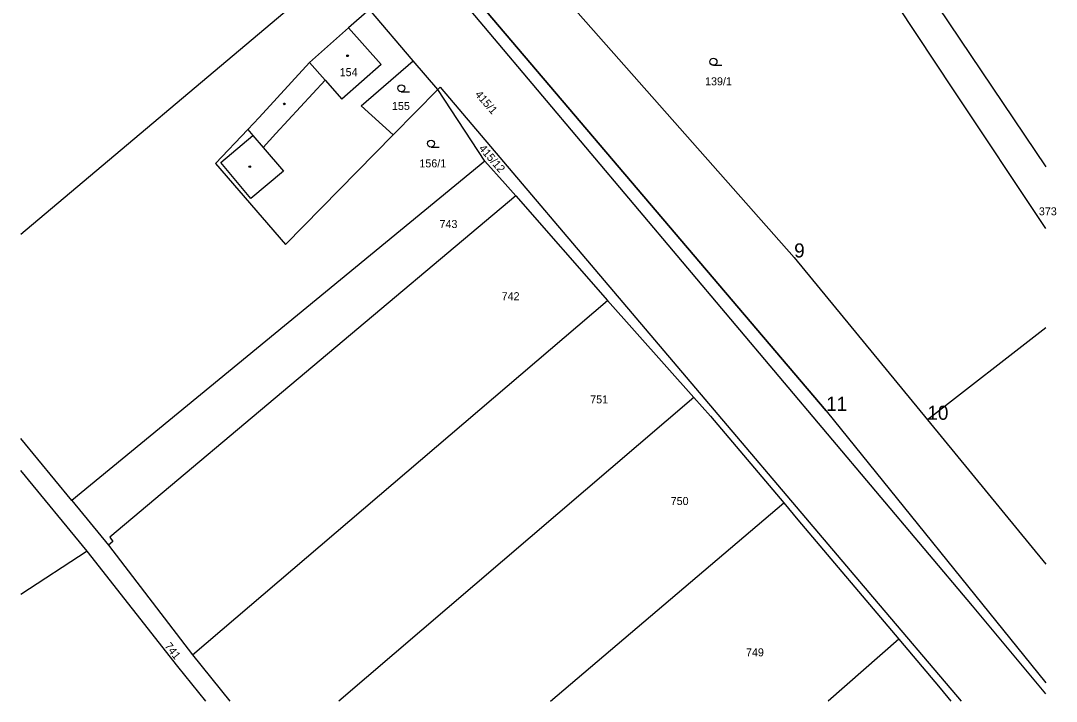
# Model space of a CAD drawing. Extents: x -504601 to -503665, y -1079870 to -1078626.
# Drawn here: x -504599.7 to -504379.8, y -1078928.2 to -1078783.7 of the extents above; entities that cross this region are included whole.
import ezdxf

# ---------------------------------------------------------------- set-up
doc = ezdxf.new("R2010")
doc.units = 0
for name, color, linetype in [('Hranice parcel', 7, 'Continuous'), ('Parcelní čísla', 7, 'Continuous'), ('Vnitřní kresba', 7, 'Continuous'), ('Vrstva 31', 7, 'Continuous'), ('Vrstva 32', 7, 'Continuous'), ('Vrstva 54', 7, 'Continuous'), ('Značky budov', 7, 'Continuous'), ('Značky kultur', 7, 'Continuous')]:
    doc.layers.add(name, color=color, linetype=linetype)

msp = doc.modelspace()

# ---------------------------------------------------------------- linework, layer by layer
at = {"layer": 'Hranice parcel'}
for p, q in [((-504599.72, -1078829.02), (-504538.29, -1078777.24)), ((-504516.36, -1078792.2), (-504525.66, -1078781.28)), ((-504511.18, -1078798.28), (-504516.36, -1078792.2)), ((-504520.67, -1078807.94), (-504511.18, -1078798.28)), ((-504511.18, -1078798.28), (-504510.65, -1078797.8)), ((-504501.14, -1078813.49), (-504511.18, -1078798.28)), ((-504494.6, -1078820.86), (-504475.16, -1078843.09)), ((-504563.23, -1078918.36), (-504475.16, -1078843.09)), ((-504475.16, -1078843.09), (-504456.8, -1078863.69)), ((-504382.03, -1078848.9), (-504407.21, -1078868.45)), ((-504456.8, -1078863.69), (-504532.18, -1078928.23)), ((-504407.21, -1078868.45), (-504382.03, -1078899.14)), ((-504588.84, -1078885.56), (-504599.72, -1078872.39)), ((-504588.84, -1078885.56), (-504581.08, -1078895.08)), ((-504487.22, -1078928.23), (-504437.71, -1078886.11)), ((-504581.08, -1078895.08), (-504563.23, -1078918.36)), ((-504413.27, -1078915.05), (-504428.26, -1078928.23)), ((-504563.23, -1078918.36), (-504555.31, -1078928.23))]:
    msp.add_line(p, q, dxfattribs=at)
for points in [[(-504597.09, -1078667.4), (-504514.19, -1078765.94), (-504428.7, -1078866.55), (-504382.03, -1078924.33)], [(-504382.03, -1078926.66), (-504397.6, -1078907.92), (-504520.79, -1078761.79), (-504523.08, -1078763.96), (-504532.75, -1078752.34), (-504530.29, -1078750.16), (-504595.19, -1078673.8)], [(-504382.03, -1078827.83), (-504401.66, -1078798.36), (-504417.34, -1078774.6), (-504425.36, -1078757.05)], [(-504417.76, -1078758.69), (-504414.04, -1078766.61), (-504407.2, -1078777.37), (-504382.03, -1078814.7)], [(-504525.66, -1078781.28), (-504530.11, -1078785.23), (-504538.39, -1078792.59), (-504549.12, -1078804.23), (-504551.53, -1078806.79), (-504558.35, -1078814.04), (-504543.52, -1078831.19), (-504520.67, -1078807.94)], [(-504481.39, -1078782.11), (-504435.49, -1078833.98), (-504407.21, -1078868.45)], [(-504520.67, -1078807.94), (-504527.41, -1078801.79), (-504516.36, -1078792.2)], [(-504510.65, -1078797.8), (-504419.66, -1078905.09), (-504400.02, -1078928.23)], [(-504501.14, -1078813.49), (-504535, -1078841.31), (-504588.84, -1078885.56)], [(-504501.14, -1078813.49), (-504496.83, -1078818.31), (-504494.6, -1078820.86)], [(-504494.6, -1078820.86), (-504580.77, -1078893.36), (-504580.15, -1078894.29), (-504581.08, -1078895.08)], [(-504456.8, -1078863.69), (-504453.26, -1078867.66), (-504437.71, -1078886.11)], [(-504585.64, -1078896.32), (-504599.72, -1078879.24)], [(-504437.71, -1078886.11), (-504434.71, -1078889.67), (-504413.27, -1078915.05)], [(-504585.64, -1078896.32), (-504599.72, -1078905.56)], [(-504560.44, -1078928.23), (-504566.37, -1078920.84), (-504585.64, -1078896.32)], [(-504413.27, -1078915.05), (-504404.47, -1078925.46), (-504402.2, -1078928.23)]]:
    msp.add_lwpolyline(points, dxfattribs=at)
at = {"layer": 'Vnitřní kresba'}
for p, q in [((-504530.11, -1078785.23), (-504523.22, -1078792.99)), ((-504538.39, -1078792.59), (-504535.08, -1078796.32)), ((-504523.22, -1078792.99), (-504531.51, -1078800.35)), ((-504545.52, -1078807.65), (-504535.08, -1078796.32)), ((-504535.08, -1078796.32), (-504531.51, -1078800.35)), ((-504551.53, -1078806.79), (-504550.45, -1078808.05)), ((-504548.25, -1078810.61), (-504545.52, -1078807.65)), ((-504557.26, -1078813.77), (-504550.45, -1078808.05)), ((-504550.45, -1078808.05), (-504548.25, -1078810.61)), ((-504548.25, -1078810.61), (-504543.94, -1078815.64)), ((-504550.83, -1078821.43), (-504557.26, -1078813.77)), ((-504543.94, -1078815.64), (-504550.83, -1078821.43))]:
    msp.add_line(p, q, dxfattribs=at)
at = {"layer": 'Vrstva 31'}
for p, q in [((-504435.49, -1078833.98), (-504435.49, -1078833.98)), ((-504428.7, -1078866.55), (-504428.7, -1078866.55)), ((-504407.21, -1078868.45), (-504407.21, -1078868.45))]:
    msp.add_line(p, q, dxfattribs=at)
at = {"layer": 'Vrstva 54'}
for points in [[(-504428.7, -1078866.55), (-504514.19, -1078765.94), (-504597.09, -1078667.4)], [(-504558.84, -1078682.13), (-504530.83, -1078717.69), (-504515.48, -1078737.7), (-504513.37, -1078735.66), (-504512.16, -1078737.29), (-504507.63, -1078743.89), (-504506.21, -1078745.96), (-504510.04, -1078749.73), (-504485.94, -1078776.97), (-504483.44, -1078779.79), (-504481.39, -1078782.11), (-504435.49, -1078833.98), (-504407.21, -1078868.45)]]:
    msp.add_lwpolyline(points, dxfattribs=at)
at = {"layer": 'Značky budov'}
for centre in [(-504530.32, -1078791.14), (-504543.75, -1078801.36), (-504551.08, -1078814.7)]:
    msp.add_circle(centre, 0.175, dxfattribs=at)
at = {"layer": 'Značky kultur'}
for p, q in [((-504452.63, -1078793.16), (-504450.88, -1078793.16)), ((-504518.92, -1078798.79), (-504517.17, -1078798.79)), ((-504512.6, -1078810.54), (-504510.85, -1078810.54))]:
    msp.add_line(p, q, dxfattribs=at)
for centre in [(-504452.63, -1078792.41), (-504518.92, -1078798.04), (-504512.6, -1078809.79)]:
    msp.add_circle(centre, 0.75, dxfattribs=at)

# ---------------------------------------------------------------- texts
at = {"layer": 'Parcelní čísla'}
for s, p in [('154', (-504531.99, -1078795.47)), ('139/1', (-504454.41, -1078797.41)), ('155', (-504520.89, -1078802.65)), ('156/1', (-504515.07, -1078814.84)), ('373', (-504383.53, -1078825.02)), ('743', (-504510.79, -1078827.72)), ('742', (-504497.6, -1078843.05)), ('751', (-504478.8, -1078864.96)), ('750', (-504461.7, -1078886.54)), ('749', (-504445.72, -1078918.68))]:
    msp.add_text(s, height=1.7, dxfattribs=at).set_placement(p)
for s, rotation, p in [('415/1', 311, (-504503.37, -1078799.42)), ('415/12', 311, (-504502.56, -1078810.9)), ('741', 308, (-504569.28, -1078916.53))]:
    msp.add_text(s, height=1.7, rotation=rotation, dxfattribs=at).set_placement(p)
at = {"layer": 'Vrstva 32'}
for s, p in [('9', (-504435.49, -1078833.98)), ('11', (-504428.7, -1078866.55)), ('10', (-504407.21, -1078868.45))]:
    msp.add_text(s, height=3, dxfattribs=at).set_placement(p)

doc.saveas('drawing.dxf')
